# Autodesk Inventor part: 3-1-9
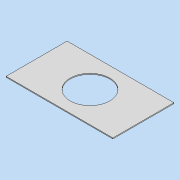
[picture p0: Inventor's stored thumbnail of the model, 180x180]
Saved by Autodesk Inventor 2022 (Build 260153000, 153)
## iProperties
Created: 2021-07
Part Number: 3-1-9
Material: 一般
Document SubType Name: Modeling
Designer: DesignLab
Density: 1 g/cm^3
Appearance: 既定
Author: DesignLab
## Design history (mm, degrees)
sketch "スケッチ1"
  geometry: L1 (0, 0)-(-350, 0); L2 (-350, 0)-(-350, -200); L3 (-350, -200)-(0, -200); L4 (0, -200)-(0, 0)
  constraints: 8 end point, 2 parallel, 1 horizontal, 1 perpendicular
  dimensions: "d0" = 350 distance of L3.end L2.end; "d1" = 200 distance of L2.end L1.end
extrude "押し出し1" new body sketch "スケッチ1" distance "d2" = 3; taper "d3" = 0 deg
sketch "スケッチ2"
  geometry: L1 (350, 200)-(0, 200) reference; L2 (0, 200)-(0, 0) reference; C1 r 65 at (175, 100); 2 further points
  constraints: 2 midpoint, 1 centre point
  dimensions: "d4" = 130 diameter of C1; "d9" = 175 distance from line of C1.centre L2 (= 0.5 x d0); "d10" = 100 distance from line of C1.centre L1 (= 0.5 x d1)
extrude "押し出し2" cut sketch "スケッチ2" distance "d7" = 3; taper "d8" = 0 deg
node "ソリッド1"
